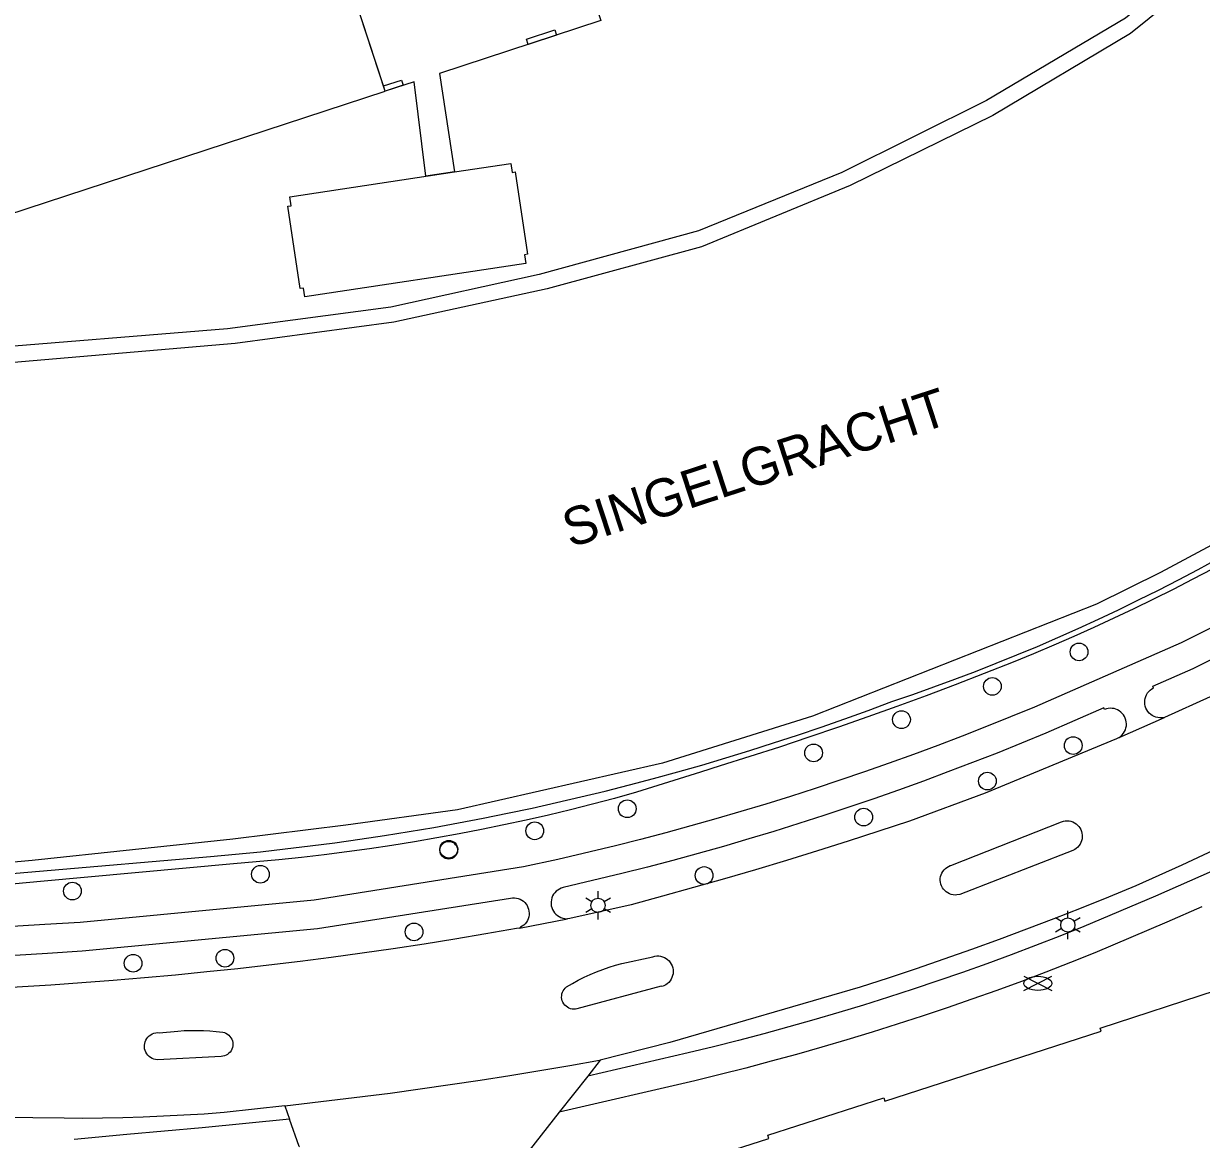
# Model space of a CAD drawing. Extents: x 122462 to 123306, y 485548 to 486417.
# Drawn here: x 123007.5 to 123082, y 486097.3 to 486167.9 of the extents above; entities that cross this region are included whole.
import ezdxf

# ---------------------------------------------------------------- set-up
doc = ezdxf.new("R2010")
doc.units = 0
for name, color, linetype in [('Level 1', 7, 'Continuous'), ('Level 10', 7, 'Continuous'), ('Level 15', 7, 'Continuous'), ('Level 16', 7, 'Continuous'), ('Level 17', 7, 'Continuous'), ('Level 19', 7, 'Continuous'), ('Level 2', 7, 'Continuous'), ('Level 21', 7, 'Continuous'), ('Level 50', 7, 'Continuous'), ('Level 52', 7, 'Continuous'), ('Level 53', 7, 'Continuous'), ('N-WE-GR-BOOM_STAM-G', 7, 'Continuous')]:
    doc.layers.add(name, color=color, linetype=linetype)

msp = doc.modelspace()

# ---------------------------------------------------------------- linework, layer by layer
at = {"layer": 'Level 1'}
msp.add_lwpolyline([(123047.864, 486084.514), (123046.91, 486086.65), (123046.61, 486086.809), (123047.299, 486088.323), (123045.88, 486088.959), (123046.572, 486090.499), (123046.664, 486090.458), (123047.169, 486091.581), (123047.326, 486091.511), (123048.034, 486093.086), (123047.877, 486093.156), (123048.382, 486094.28), (123048.299, 486094.317), (123048.89, 486095.632), (123050.361, 486094.971), (123051.048, 486096.5), (123051.426, 486096.369), (123054.647, 486097.413), (123054.59, 486097.62), (123061.92, 486099.979), (123061.99, 486099.766), (123075.665, 486104.189), (123075.6, 486104.39), (123082.949, 486106.779)], dxfattribs=at)
at = {"layer": 'Level 10'}
msp.add_lwpolyline([(123032.978, 486158.22), (123032.232, 486164.193), (123030.399, 486163.594), (123026.409, 486175.777), (123030.453, 486177.101), (123029.82, 486183.151), (123031.298, 486183.381), (123031.905, 486177.576), (123035.457, 486178.739), (123040.043, 486180.241), (123044.032, 486168.057), (123033.844, 486164.721), (123034.778, 486158.491), (123032.978, 486158.22)], dxfattribs=at)
at = {"layer": 'Level 15'}
for points in [[(123125.046, 486171.985), (123124.968, 486172.042), (123122.38, 486168.809), (123104.97, 486150.469), (123101.5, 486147.339), (123097.78, 486144.409), (123093.15, 486141.209), (123085.31, 486136.329), (123079.41, 486133.169), (123075.37, 486131.179), (123057.42, 486124.099), (123047.93, 486121.129), (123034.98, 486118.169), (123027.92, 486117.199), (123020.77, 486116.329), (123008.09, 486114.969), (122994.95, 486113.769), (122968.19, 486112.329), (122947.31, 486111.219), (122945.01, 486110.939), (122936.24, 486109.969), (122930.59, 486109.269), (122923.91, 486108.069)], [(122997.72, 486113.385), (123008.543, 486114.309), (123019.365, 486115.232), (123020.94, 486115.374), (123022.514, 486115.532), (123024.087, 486115.706), (123025.657, 486115.895), (123027.226, 486116.099), (123028.792, 486116.319), (123030.356, 486116.555), (123031.918, 486116.805), (123033.477, 486117.072), (123035.034, 486117.353), (123036.588, 486117.651), (123038.138, 486117.963), (123039.686, 486118.291), (123041.23, 486118.634), (123042.771, 486118.992), (123044.308, 486119.366), (123045.841, 486119.754), (123047.371, 486120.158), (123048.896, 486120.577), (123050.417, 486121.011), (123051.934, 486121.46), (123053.446, 486121.924), (123054.954, 486122.403), (123056.457, 486122.896), (123057.955, 486123.405), (123059.447, 486123.928), (123060.935, 486124.466), (123062.417, 486125.019), (123063.749, 486125.473), (123065.076, 486125.943), (123066.398, 486126.427), (123067.714, 486126.926), (123069.024, 486127.44), (123070.329, 486127.968), (123071.627, 486128.511), (123072.92, 486129.068), (123074.206, 486129.64), (123075.485, 486130.226), (123076.758, 486130.827), (123078.024, 486131.442), (123079.284, 486132.071), (123080.536, 486132.714), (123081.78, 486133.371), (123083.018, 486134.042)]]:
    msp.add_lwpolyline(points, dxfattribs=at)
at = {"layer": 'Level 16'}
msp.add_lwpolyline([(123121.451, 486219.611), (123111.078, 486204.408), (123108.132, 486199.925), (123097.567, 486185.52), (123093.77, 486181.517), (123089.068, 486176.699), (123085.87, 486173.994), (123077.516, 486167.246), (123068.815, 486162.068), (123059.792, 486157.639), (123050.392, 486153.767), (123040.634, 486151.107), (123030.95, 486148.992), (123020.912, 486147.653), (123004.699, 486146.258), (122993.774, 486145.686)], dxfattribs=at)
at = {"layer": 'Level 17'}
for p, q in [((123076.798, 486122.745), (123079.669, 486124.023)), ((123038.885, 486110.705), (123041.93, 486111.294)), ((123043.996, 486102.352), (123043.213, 486101.346)), ((123043.213, 486101.346), (123041.404, 486099.08)), ((123024.059, 486099.481), (123024.358, 486098.626)), ((123041.404, 486099.08), (123036.557, 486092.89))]:
    msp.add_line(p, q, dxfattribs=at)
for points in [[(123082.673, 486133.397), (123081.445, 486132.748), (123080.209, 486132.113), (123078.967, 486131.491), (123077.719, 486130.882), (123076.463, 486130.286), (123075.202, 486129.704), (123073.934, 486129.136), (123072.661, 486128.581), (123071.381, 486128.04), (123070.096, 486127.512), (123068.269, 486126.789), (123066.435, 486126.081), (123064.596, 486125.387), (123062.752, 486124.709), (123060.902, 486124.046), (123059.046, 486123.397), (123057.186, 486122.764), (123055.32, 486122.146), (123053.449, 486121.544), (123051.574, 486120.956), (123050.334, 486120.551), (123046.291, 486119.286), (123044.903, 486118.904), (123043.511, 486118.538), (123042.115, 486118.186), (123040.715, 486117.85), (123039.311, 486117.529), (123037.905, 486117.224), (123036.495, 486116.934), (123035.081, 486116.659), (123033.665, 486116.4), (123032.246, 486116.157), (123030.825, 486115.928), (123029.401, 486115.716), (123027.975, 486115.519), (123026.547, 486115.338), (123025.117, 486115.172), (123023.685, 486115.022), (123022.252, 486114.888), (123020.817, 486114.769), (123008.608, 486113.648), (123000.932, 486112.943)], [(123085.112, 486130.952), (123080.703, 486128.731), (123071.446, 486124.675), (123069.927, 486124.049), (123068.402, 486123.437), (123066.872, 486122.839), (123065.337, 486122.254), (123063.796, 486121.682), (123062.251, 486121.124), (123060.701, 486120.58), (123059.146, 486120.05), (123057.586, 486119.533), (123056.022, 486119.03), (123054.453, 486118.541), (123052.881, 486118.066), (123051.304, 486117.605), (123049.723, 486117.158), (123048.138, 486116.725), (123046.549, 486116.306), (123044.957, 486115.901), (123041.313, 486115.039), (123039.136, 486114.573), (123025.905, 486112.468), (123011.114, 486111.059), (123008.881, 486110.922), (122954.466, 486107.583)], [(123079.669, 486124.023), (123079.49, 486124.001), (123079.365, 486123.998), (123079.24, 486124.01), (123079.118, 486124.038), (123079, 486124.082), (123078.889, 486124.14), (123078.786, 486124.211), (123078.692, 486124.295), (123078.611, 486124.39), (123078.541, 486124.495), (123078.486, 486124.607), (123078.445, 486124.726), (123078.419, 486124.848), (123078.409, 486124.973), (123078.415, 486125.099), (123078.437, 486125.222), (123078.474, 486125.342), (123078.526, 486125.456), (123078.592, 486125.563), (123078.671, 486125.66), (123078.762, 486125.747), (123078.863, 486125.822), (123078.972, 486125.883), (123078.926, 486125.987), (123081.47, 486127.102), (123085.91, 486129.339)], [(123082.536, 486125.329), (123079.669, 486124.023)], [(123076.798, 486122.745), (123076.899, 486122.824), (123076.989, 486122.915), (123077.068, 486123.015), (123077.134, 486123.125), (123077.187, 486123.242), (123077.225, 486123.364), (123077.248, 486123.49), (123077.254, 486123.611), (123077.245, 486123.733), (123077.221, 486123.852), (123077.183, 486123.967), (123077.131, 486124.077), (123077.066, 486124.18), (123076.989, 486124.274), (123076.902, 486124.359), (123076.805, 486124.432), (123076.699, 486124.492), (123076.587, 486124.54), (123076.471, 486124.573), (123076.351, 486124.592), (123076.229, 486124.597), (123076.108, 486124.586), (123075.989, 486124.561), (123075.874, 486124.522), (123075.827, 486124.629), (123072.154, 486123.02), (123070.618, 486122.387), (123069.076, 486121.768), (123067.528, 486121.162), (123065.975, 486120.571), (123064.417, 486119.993), (123062.854, 486119.428), (123061.287, 486118.878), (123059.714, 486118.342), (123058.136, 486117.819), (123056.554, 486117.311), (123054.968, 486116.816), (123053.377, 486116.336), (123051.782, 486115.87), (123050.183, 486115.418), (123048.58, 486114.98), (123046.973, 486114.556), (123045.363, 486114.147), (123041.652, 486113.263), (123041.532, 486113.227), (123041.417, 486113.175), (123041.31, 486113.11), (123041.212, 486113.032), (123041.124, 486112.942), (123041.049, 486112.842), (123040.986, 486112.733), (123040.938, 486112.617), (123040.905, 486112.496), (123040.888, 486112.371), (123040.886, 486112.246), (123040.9, 486112.121), (123040.93, 486111.999), (123040.975, 486111.882), (123041.035, 486111.771), (123041.107, 486111.669), (123041.193, 486111.577), (123041.289, 486111.496), (123041.394, 486111.428), (123041.508, 486111.374), (123041.627, 486111.334), (123041.75, 486111.31), (123041.93, 486111.294)], [(123076.798, 486122.745), (123076.635, 486122.672), (123068.323, 486119.232), (123063.551, 486117.468), (123061.613, 486116.826), (123059.671, 486116.198), (123057.724, 486115.584), (123055.773, 486114.983), (123053.818, 486114.395), (123051.859, 486113.822), (123049.896, 486113.261), (123047.929, 486112.715), (123045.958, 486112.182), (123042.072, 486111.321), (123041.93, 486111.294)], [(123089.528, 486118.791), (123080.747, 486114.672), (123077.839, 486113.366), (123076.123, 486112.661), (123074.402, 486111.971), (123072.674, 486111.296), (123070.942, 486110.634), (123069.203, 486109.988), (123067.459, 486109.356), (123065.71, 486108.738), (123063.956, 486108.136), (123062.197, 486107.548), (123060.433, 486106.975), (123048.393, 486103.481), (123043.996, 486102.352)], [(123089.828, 486117.467), (123079.09, 486112.721), (123074.57, 486110.798), (123073.044, 486110.19), (123071.512, 486109.596), (123069.975, 486109.017), (123068.432, 486108.452), (123066.884, 486107.901), (123065.332, 486107.365), (123063.774, 486106.844), (123062.211, 486106.337), (123060.644, 486105.844), (123059.072, 486105.367), (123057.496, 486104.904), (123055.915, 486104.456), (123054.33, 486104.023), (123052.742, 486103.604), (123051.149, 486103.201), (123049.553, 486102.812), (123043.213, 486101.346)], [(123066.422, 486112.793), (123066.302, 486112.803), (123066.184, 486112.829), (123066.071, 486112.869), (123065.963, 486112.923), (123065.863, 486112.991), (123065.772, 486113.07), (123065.692, 486113.16), (123065.623, 486113.259), (123065.568, 486113.367), (123065.526, 486113.48), (123065.499, 486113.597), (123065.487, 486113.717), (123065.491, 486113.838), (123065.509, 486113.957), (123065.542, 486114.073), (123065.589, 486114.184), (123065.65, 486114.289), (123065.723, 486114.384), (123065.808, 486114.47), (123065.903, 486114.544), (123066.007, 486114.606), (123066.117, 486114.655), (123066.16, 486114.655), (123073.155, 486117.429), (123073.27, 486117.463), (123073.389, 486117.482), (123073.509, 486117.487), (123073.629, 486117.477), (123073.746, 486117.452), (123073.86, 486117.413), (123073.968, 486117.361), (123074.068, 486117.295), (123074.16, 486117.218), (123074.242, 486117.13), (123074.312, 486117.032), (123074.37, 486116.927), (123074.415, 486116.815), (123074.445, 486116.699), (123074.461, 486116.58), (123074.462, 486116.46), (123074.448, 486116.341), (123074.42, 486116.224), (123074.377, 486116.111), (123074.322, 486116.005), (123074.253, 486115.906), (123074.173, 486115.817), (123074.083, 486115.738), (123073.983, 486115.671), (123073.876, 486115.616), (123066.715, 486112.83), (123066.543, 486112.797), (123066.422, 486112.793)], [(122980.469, 486107.367), (123009.06, 486109.129), (123011.255, 486109.264), (123026.132, 486110.681), (123038.332, 486112.604), (123038.453, 486112.619), (123038.576, 486112.62), (123038.697, 486112.605), (123038.815, 486112.575), (123038.929, 486112.53), (123039.037, 486112.472), (123039.136, 486112.401), (123039.226, 486112.318), (123039.305, 486112.225), (123039.372, 486112.123), (123039.426, 486112.013), (123039.465, 486111.897), (123039.49, 486111.778), (123039.5, 486111.656), (123039.495, 486111.534), (123039.475, 486111.413), (123039.439, 486111.296), (123039.39, 486111.184), (123039.327, 486111.079), (123039.252, 486110.983), (123039.165, 486110.897), (123039.068, 486110.822), (123038.963, 486110.76), (123038.885, 486110.705)], [(123082.022, 486112.049), (123079.806, 486111.07), (123075.26, 486109.135), (123073.717, 486108.52), (123072.168, 486107.92), (123070.614, 486107.334), (123069.054, 486106.763), (123067.489, 486106.206), (123065.919, 486105.664), (123064.344, 486105.137), (123062.764, 486104.624), (123061.179, 486104.126), (123059.59, 486103.643), (123057.996, 486103.175), (123056.398, 486102.722), (123054.795, 486102.284), (123053.189, 486101.861), (123051.579, 486101.453), (123049.965, 486101.06), (123041.404, 486099.08)], [(123038.885, 486110.705), (123038.712, 486110.672), (123036.763, 486110.333), (123034.811, 486110.008), (123032.856, 486109.698), (123030.9, 486109.402), (123028.941, 486109.121), (123026.981, 486108.854), (123025.018, 486108.601), (123023.054, 486108.363), (123021.088, 486108.139), (123019.12, 486107.93), (123017.151, 486107.735), (123015.181, 486107.555), (123013.209, 486107.389), (123011.236, 486107.238), (123009.262, 486107.101), (122980.378, 486105.385)], [(123042.332, 486105.581), (123042.225, 486105.589), (123042.119, 486105.611), (123042.018, 486105.648), (123041.922, 486105.699), (123041.835, 486105.762), (123041.757, 486105.837), (123041.69, 486105.922), (123041.636, 486106.015), (123041.595, 486106.115), (123041.568, 486106.22), (123041.556, 486106.327), (123041.559, 486106.435), (123041.577, 486106.542), (123041.609, 486106.645), (123041.656, 486106.742), (123041.715, 486106.832), (123041.786, 486106.913), (123041.868, 486106.984), (123042.232, 486107.201), (123042.602, 486107.405), (123042.98, 486107.597), (123043.364, 486107.775), (123043.754, 486107.94), (123044.149, 486108.092), (123044.549, 486108.23), (123044.954, 486108.354), (123045.363, 486108.464), (123047.32, 486108.896), (123047.44, 486108.927), (123047.564, 486108.942), (123047.688, 486108.941), (123047.811, 486108.925), (123047.931, 486108.893), (123048.046, 486108.847), (123048.155, 486108.786), (123048.255, 486108.712), (123048.344, 486108.627), (123048.423, 486108.53), (123048.488, 486108.424), (123048.54, 486108.312), (123048.577, 486108.193), (123048.598, 486108.071), (123048.604, 486107.947), (123048.595, 486107.823), (123048.57, 486107.701), (123048.529, 486107.584), (123048.475, 486107.472), (123048.406, 486107.368), (123048.325, 486107.274), (123048.233, 486107.191), (123048.131, 486107.12), (123048.021, 486107.062), (123047.905, 486107.019), (123047.847, 486107.028), (123042.518, 486105.603), (123042.44, 486105.588), (123042.332, 486105.581)], [(123016.001, 486102.377), (123015.888, 486102.39), (123015.777, 486102.418), (123015.671, 486102.461), (123015.571, 486102.517), (123015.48, 486102.586), (123015.399, 486102.666), (123015.329, 486102.757), (123015.272, 486102.856), (123015.228, 486102.961), (123015.199, 486103.072), (123015.184, 486103.185), (123015.185, 486103.299), (123015.201, 486103.413), (123015.231, 486103.523), (123015.276, 486103.628), (123015.334, 486103.726), (123015.405, 486103.816), (123015.488, 486103.895), (123015.579, 486103.963), (123015.68, 486104.018), (123015.786, 486104.059), (123015.897, 486104.086), (123016.011, 486104.098), (123016.125, 486104.095), (123017.289, 486104.198), (123017.695, 486104.224), (123018.102, 486104.238), (123018.509, 486104.239), (123018.916, 486104.228), (123019.322, 486104.205), (123019.728, 486104.17), (123020.132, 486104.123), (123020.236, 486104.097), (123020.336, 486104.057), (123020.429, 486104.003), (123020.514, 486103.937), (123020.589, 486103.86), (123020.653, 486103.774), (123020.703, 486103.679), (123020.741, 486103.578), (123020.764, 486103.473), (123020.772, 486103.366), (123020.765, 486103.259), (123020.743, 486103.153), (123020.707, 486103.052), (123020.658, 486102.957), (123020.595, 486102.869), (123020.521, 486102.791), (123020.437, 486102.724), (123020.345, 486102.669), (123020.246, 486102.628), (123020.142, 486102.601), (123020.035, 486102.588), (123016.001, 486102.377)], [(123024.059, 486099.481), (123030.707, 486100.282), (123032.605, 486100.541), (123034.502, 486100.813), (123036.396, 486101.096), (123038.289, 486101.391), (123040.18, 486101.699), (123042.069, 486102.018), (123043.956, 486102.35), (123043.996, 486102.352)], [(123024.059, 486099.481), (123020.233, 486099.044), (123018.951, 486098.952), (123017.667, 486098.874), (123016.383, 486098.809), (123015.098, 486098.757), (123013.813, 486098.718), (123012.528, 486098.692), (123011.242, 486098.68), (123010.102, 486098.693), (122994.194, 486098.868), (122994.105, 486098.873), (122994.016, 486098.863), (122993.931, 486098.84), (122993.849, 486098.803), (122993.775, 486098.754), (122993.71, 486098.693), (122992.227, 486097.137)], [(123024.358, 486098.626), (123018.841, 486098.086), (123014.077, 486097.657), (123010.744, 486097.341)], [(123024.984, 486096.879), (123024.959, 486096.899), (123024.358, 486098.626)]]:
    msp.add_lwpolyline(points, dxfattribs=at)
at = {"layer": 'Level 19'}
msp.add_lwpolyline([(123105.058, 486197.081), (123096.687, 486186.104), (123093.037, 486182.067), (123088.635, 486177.644), (123077.195, 486168.208), (123068.416, 486163.011), (123059.259, 486158.459), (123050.208, 486154.764), (123040.14, 486152.009), (123030.756, 486149.944), (123020.43, 486148.568), (123004.328, 486147.27), (122993.462, 486146.661)], dxfattribs=at)
at = {"layer": 'Level 2'}
for p, q in [((123030.29, 486163.926), (123026.518, 486175.445)), ((123030.399, 486163.594), (123030.29, 486163.926))]:
    msp.add_line(p, q, dxfattribs=at)
for points in [[(123023.153, 486220.707), (123018.657, 486219.237), (123018.622, 486219.342), (123017.89, 486219.102), (123018.064, 486218.569), (122985.338, 486207.834), (122985.304, 486207.938), (122984.448, 486207.657), (122984.696, 486206.896), (122984.8, 486206.93), (123001.815, 486154.962), (123001.71, 486154.927), (123001.958, 486154.166), (123002.719, 486154.414), (123002.684, 486154.518), (123030.399, 486163.594)], [(123025.321, 486150.594), (123025.236, 486151.158), (123025.038, 486151.128), (123024.254, 486156.329), (123024.452, 486156.359), (123024.367, 486156.922), (123034.778, 486158.491), (123038.337, 486159.027), (123038.422, 486158.464), (123038.619, 486158.494), (123039.403, 486153.293), (123039.206, 486153.263), (123039.291, 486152.699), (123025.321, 486150.594)]]:
    msp.add_lwpolyline(points, dxfattribs=at)
at = {"layer": 'Level 21'}
for points in [[(123039.446, 486166.555), (123039.337, 486166.889), (123041.122, 486167.473), (123041.231, 486167.14), (123039.446, 486166.555)], [(123030.29, 486163.926), (123031.439, 486164.302), (123031.547, 486163.969), (123030.399, 486163.594)]]:
    msp.add_lwpolyline(points, dxfattribs=at)
at = {"layer": 'Level 50'}
for p, q in [((123043.854, 486112.591), (123043.854, 486113.041)), ((123043.464, 486112.366), (123043.074, 486112.591)), ((123044.633, 486112.591), (123044.243, 486112.366)), ((123043.464, 486111.916), (123043.074, 486111.691)), ((123043.854, 486111.241), (123043.854, 486111.691)), ((123044.633, 486111.691), (123044.243, 486111.916)), ((123073.549, 486111.349), (123073.549, 486111.799)), ((123073.159, 486111.124), (123072.769, 486111.349)), ((123074.328, 486111.349), (123073.938, 486111.124)), ((123073.159, 486110.674), (123072.769, 486110.449)), ((123073.549, 486109.999), (123073.549, 486110.449)), ((123074.328, 486110.449), (123073.938, 486110.674))]:
    msp.add_line(p, q, dxfattribs=at)
for centre in [(123043.854, 486112.141), (123073.549, 486110.899)]:
    msp.add_circle(centre, 0.45, dxfattribs=at)
at = {"layer": 'Level 52'}
for p, q in [((123070.764, 486106.768), (123072.545, 486107.658)), ((123070.764, 486107.658), (123072.545, 486106.768))]:
    msp.add_line(p, q, dxfattribs=at)
msp.add_ellipse((123071.654, 486107.211), major_axis=(0.89, 0), ratio=0.5, dxfattribs=at)
at = {"layer": 'Level 53'}
for centre in [(123074.258, 486128.158), (123068.779, 486125.981), (123063.036, 486123.878), (123073.889, 486122.239), (123057.481, 486121.775), (123068.464, 486119.994), (123045.702, 486118.246), (123060.645, 486117.718), (123039.857, 486116.853), (123034.418, 486115.622), (123034.424, 486115.687), (123022.516, 486114.105), (123050.561, 486114.028), (123010.634, 486113.045), (123032.224, 486110.465), (123020.274, 486108.802), (123014.47, 486108.479)]:
    msp.add_circle(centre, 0.56, dxfattribs=at)

# ---------------------------------------------------------------- texts
at = {"layer": 'N-WE-GR-BOOM_STAM-G'}
msp.add_text('SINGELGRACHT', height=2.4, rotation=18.14324, dxfattribs=at).set_placement((123042.102, 486134.727))

doc.saveas('drawing.dxf')
